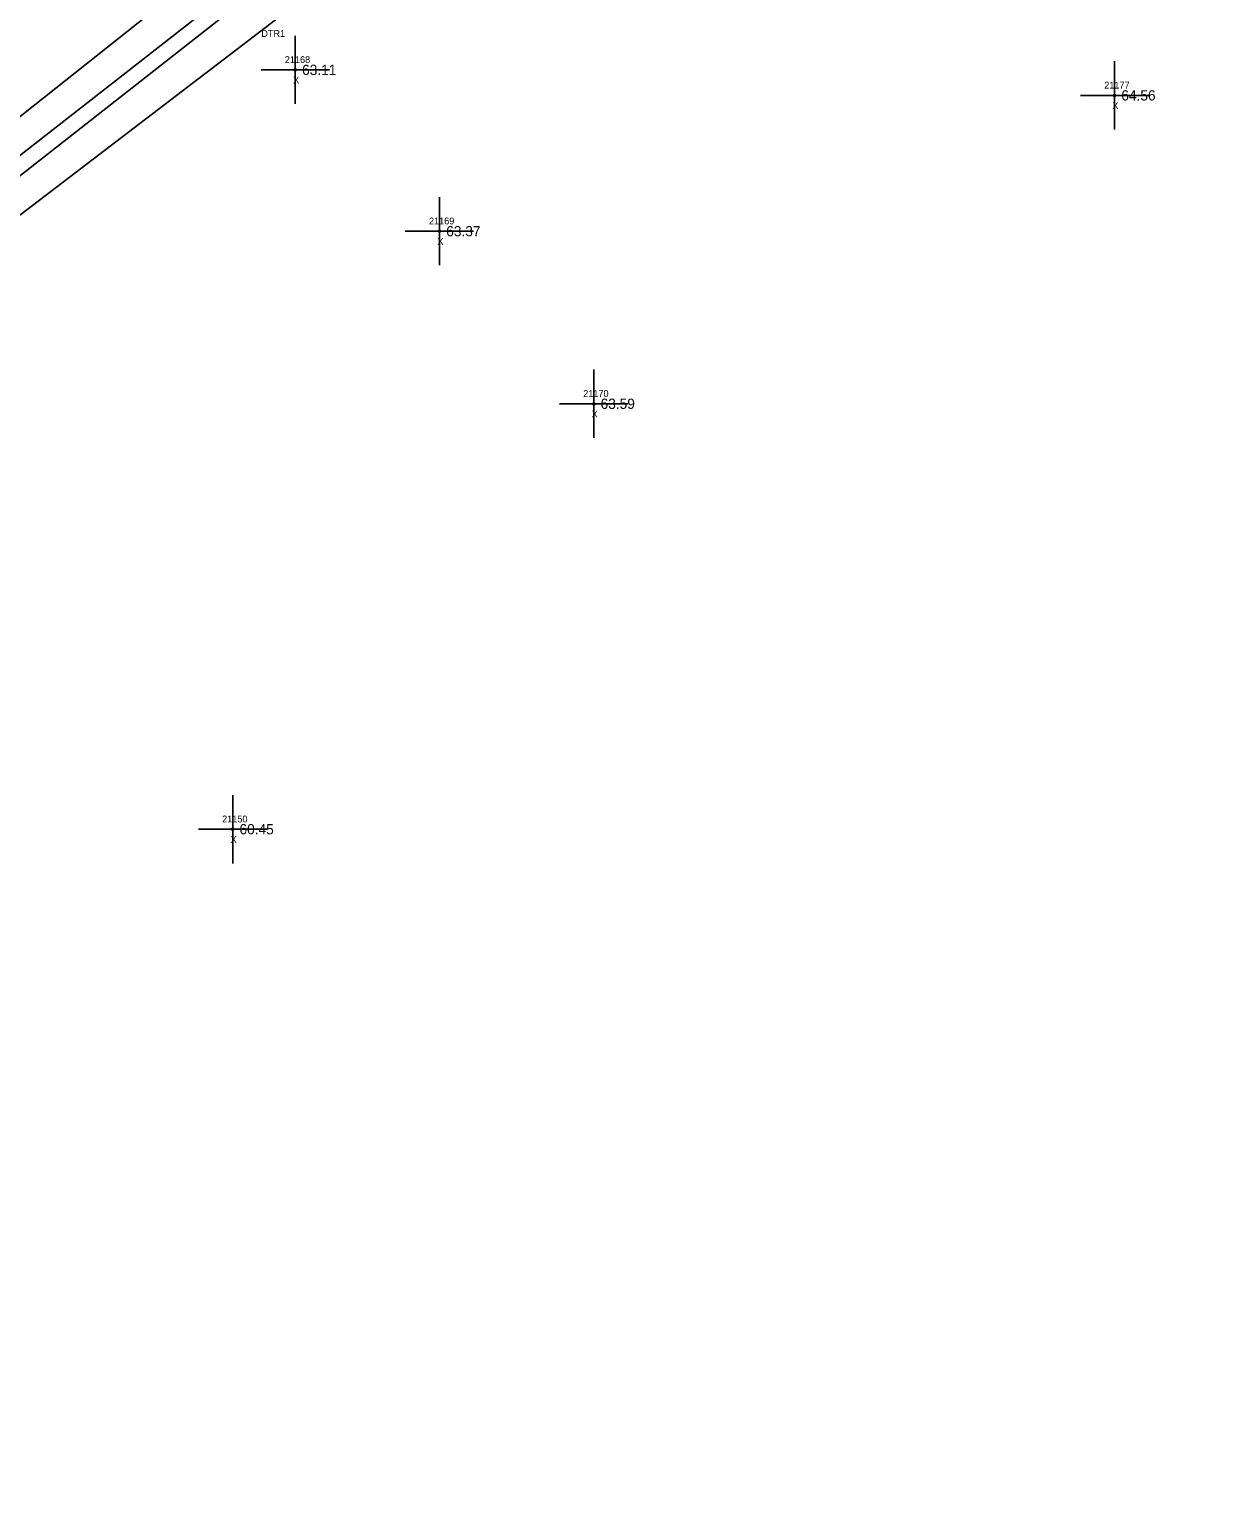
# Model space of a CAD drawing. Extents: x 2420351 to 2422725, y 845330 to 846558.
# Drawn here: x 2422489.2 to 2422664.8, y 846134.8 to 846349.5 of the extents above; entities that cross this region are included whole.
import ezdxf

# ---------------------------------------------------------------- set-up
doc = ezdxf.new("R2010")
doc.units = 0
for name, color, linetype in [('RD_EX_H2O', 7, 'Continuous'), ('RD_EX_H2O_txCode', 7, 'Continuous'), ('RD_EX_Misc', 7, 'Continuous'), ('RD_EX_Misc_txCode', 7, 'Continuous'), ('RD_EX_Road', 7, 'Continuous'), ('RD_EX_TX_Misc_ELEV', 7, 'Continuous'), ('RD_SMD_Locator', 7, 'Continuous')]:
    doc.layers.add(name, color=color, linetype=linetype)

msp = doc.modelspace()

# ---------------------------------------------------------------- linework, layer by layer
at = {"layer": 'RD_EX_H2O'}
for points in [[(2422383.12, 846248.84), (2422451.79, 846302.96), (2422519.84, 846356.14), (2422594.22, 846416.85), (2422660.96, 846466.59)], [(2422386.28, 846248.04), (2422453.27, 846301.01), (2422520.96, 846354.14), (2422596.31, 846414.61), (2422662.29, 846464.81)], [(2422383.12, 846248.84), (2422386.53, 846244.46), (2422456.45, 846298.4), (2422524.56, 846350.4), (2422601.29, 846410.12), (2422664.82, 846461.69)]]:
    msp.add_lwpolyline(points, dxfattribs=at)
at = {"layer": 'RD_EX_Misc'}
for p, q in [((2422528.11, 846338.57), (2422528.11, 846348.57)), ((2422523.11, 846343.57), (2422533.11, 846343.57)), ((2422648.1, 846334.83), (2422648.1, 846344.83)), ((2422643.1, 846339.83), (2422653.1, 846339.83)), ((2422549.22, 846314.93), (2422549.22, 846324.93)), ((2422544.22, 846319.93), (2422554.22, 846319.93)), ((2422571.83, 846289.65), (2422571.83, 846299.65)), ((2422566.83, 846294.65), (2422576.83, 846294.65)), ((2422518.94, 846227.31), (2422518.94, 846237.31)), ((2422513.94, 846232.31), (2422523.94, 846232.31))]:
    msp.add_line(p, q, dxfattribs=at)
at = {"layer": 'RD_EX_Road'}
msp.add_lwpolyline([(2421810.77, 845819.82), (2421865.31, 845853.52), (2421953.26, 845916.07), (2421995.06, 845948.03), (2422068.36, 846005.98), (2422153.46, 846073.36), (2422229.55, 846134.03), (2422245.4, 846145.63), (2422297.08, 846186.88), (2422369.77, 846243.69), (2422382.04, 846253.08), (2422449.02, 846305.97), (2422517.14, 846360.1), (2422592.58, 846419.1), (2422657.51, 846470.1)], dxfattribs=at)
at = {"layer": 'RD_SMD_Locator'}
for centre in [(2422528.11, 846343.57), (2422648.1, 846339.83), (2422549.22, 846319.93), (2422571.83, 846294.65), (2422518.94, 846232.31)]:
    msp.add_circle(centre, 0.15, dxfattribs=at)

# ---------------------------------------------------------------- texts
at = {"layer": 'RD_EX_H2O_txCode'}
msp.add_text('DTR1', height=1, dxfattribs=at).set_placement((2422523.13, 846348.4))
at = {"layer": 'RD_EX_Misc_txCode'}
for s, p in [('21168', (2422526.57, 846344.57)), ('X', (2422527.79, 846341.57)), ('21177', (2422646.59, 846340.83)), ('X', (2422647.78, 846337.83)), ('21169', (2422547.69, 846320.93)), ('X', (2422548.91, 846317.93)), ('21170', (2422570.28, 846295.65)), ('X', (2422571.51, 846292.65)), ('21150', (2422517.39, 846233.31)), ('X', (2422518.63, 846230.31))]:
    msp.add_text(s, height=1, dxfattribs=at).set_placement(p)
at = {"layer": 'RD_EX_TX_Misc_ELEV'}
for s, p in [('63.11', (2422529.11, 846342.82)), ('64.56', (2422649.1, 846339.08)), ('63.37', (2422550.22, 846319.18)), ('63.59', (2422572.83, 846293.9)), ('60.45', (2422519.94, 846231.56))]:
    msp.add_text(s, height=1.5, dxfattribs=at).set_placement(p)

doc.saveas('drawing.dxf')
